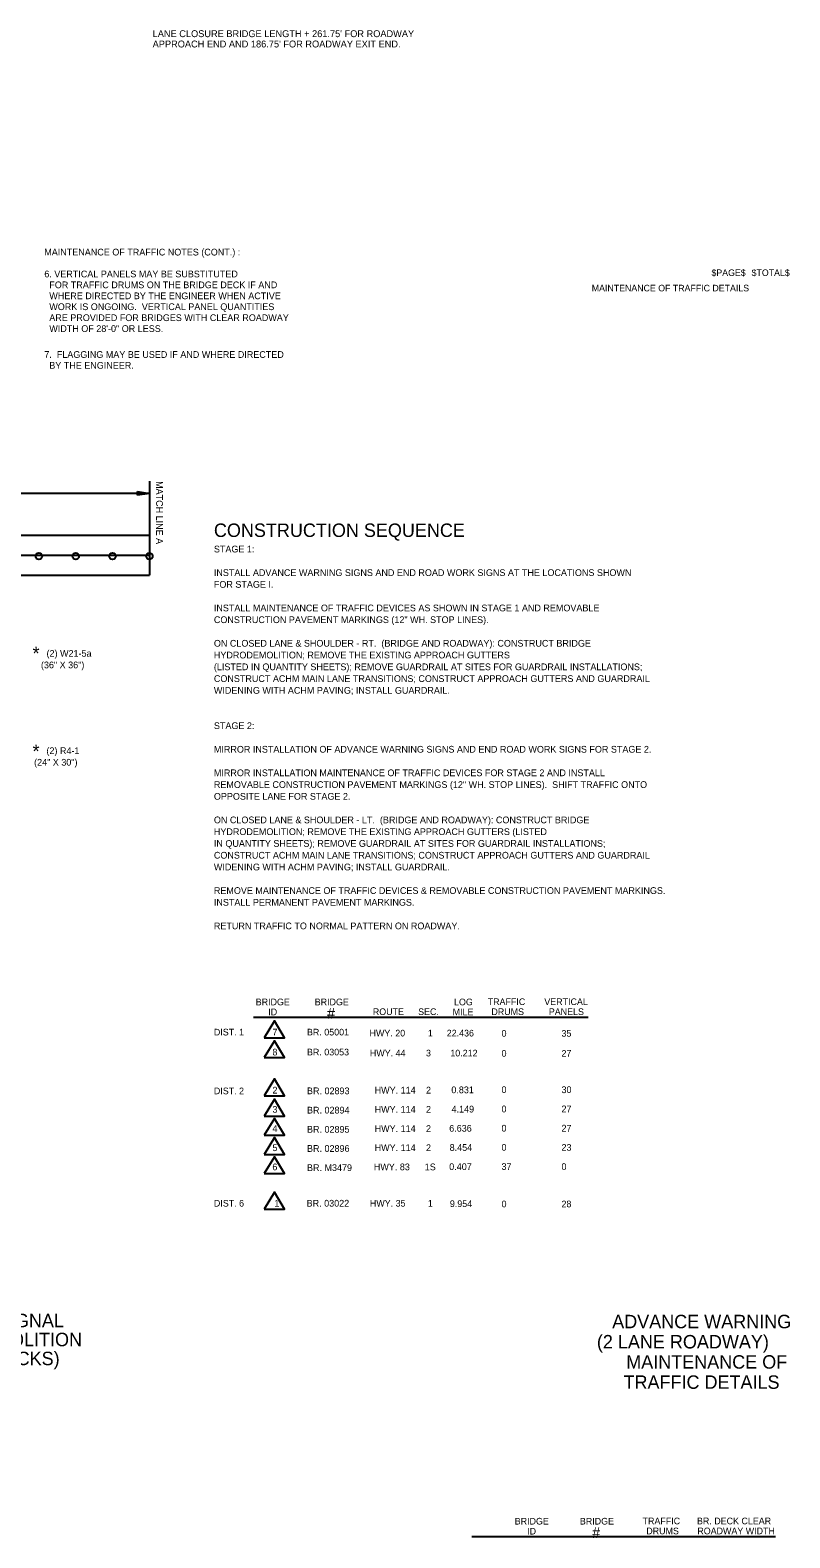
# Model space of a CAD drawing. Extents: x 1925873 to 1930787, y 596452 to 599617.
# Drawn here: x 1928734 to 1929411, y 596543 to 597888 of the extents above; entities that cross this region are included whole.
import ezdxf

# ---------------------------------------------------------------- set-up
doc = ezdxf.new("R2010")
doc.units = 0
for name, color, linetype in [('Default', 7, 'Continuous'), ('R_Border', 7, 'Continuous'), ('R_Border Prem', 7, 'Continuous')]:
    doc.layers.add(name, color=color, linetype=linetype)

msp = doc.modelspace()

# ---------------------------------------------------------------- linework, layer by layer
at = {"layer": 'Default'}
for p, q in [((1928839.9, 597485.4), (1928839.9, 597401.5)), ((1928839.9, 597474.5), (1928347.2, 597474.5)), ((1928829.3, 597472.9), (1928829.3, 597476.1)), ((1928829.3, 597476.1), (1928839.9, 597474.5)), ((1928839.9, 597474.5), (1928829.3, 597472.9)), ((1927951, 597437.1), (1928839.9, 597437.1)), ((1927951, 597419.3), (1928839.9, 597419.3)), ((1927951, 597401.5), (1928839.9, 597401.5)), ((1928942.3, 596989.1), (1928951.3, 596989.1)), ((1928942.3, 596971.3), (1928951.3, 596971.3)), ((1928942.3, 596937.4), (1928951.3, 596937.4)), ((1928942.3, 596919.2), (1928951.3, 596919.2)), ((1928942.3, 596902.1), (1928951.3, 596902.1)), ((1928942.3, 596885), (1928951.3, 596885)), ((1928942.3, 596867.9), (1928951.3, 596867.9)), ((1928942.3, 596836.3), (1928951.3, 596836.3))]:
    msp.add_line(p, q, dxfattribs=at)
for points in [[(1928951.3, 596989.1), (1928960.3, 596989.1), (1928951.3, 597004.1), (1928942.3, 596989.1)], [(1928951.3, 596971.3), (1928960.3, 596971.3), (1928951.3, 596986.3), (1928942.3, 596971.3)], [(1928951.3, 596937.4), (1928960.3, 596937.4), (1928951.3, 596952.4), (1928942.3, 596937.4)], [(1928951.3, 596919.2), (1928960.3, 596919.2), (1928951.3, 596934.2), (1928942.3, 596919.2)], [(1928951.3, 596902.1), (1928960.3, 596902.1), (1928951.3, 596917.1), (1928942.3, 596902.1)], [(1928951.3, 596885), (1928960.3, 596885), (1928951.3, 596900), (1928942.3, 596885)], [(1928951.3, 596867.9), (1928960.3, 596867.9), (1928951.3, 596882.9), (1928942.3, 596867.9)], [(1928951.3, 596836.3), (1928960.3, 596836.3), (1928951.3, 596851.3), (1928942.3, 596836.3)]]:
    msp.add_lwpolyline(points, dxfattribs=at)
for centre in [(1928741.4, 597418.5), (1928774.2, 597418.5), (1928807, 597418.5), (1928839.9, 597418.5)]:
    msp.add_circle(centre, 2.88, dxfattribs=at)
at = {"layer": 'R_Border'}
for p, q in [((1928932.8, 597007.3), (1929231.2, 597007.3)), ((1929127.5, 596544.3), (1929398, 596544.3))]:
    msp.add_line(p, q, dxfattribs=at)

# ---------------------------------------------------------------- texts
at = {"layer": 'Default'}
for s, height, rotation, p in [("LANE CLOSURE BRIDGE LENGTH + 261.75' FOR ROADWAY ", 6.14, 360, (1928842.8, 597881.3)), ("APPROACH END AND 186.75' FOR ROADWAY EXIT END.", 6.14, 360, (1928842.8, 597872.1)), ('MATCH LINE A', 6, 270, (1928845.9, 597485.4)), ('LANE CLOSURE WITH PORTABLE TRAFFIC SIGNAL ', 12, 360, (1928368.7, 596730.9)), ('SYSTEM & TRAFFIC DRUMS FOR HYDRODEMOLITION', 12, 360, (1928362.6, 596714)), ('(VAR. CLEAR ROADWAY ON THE BRIDGE DECKS)', 12, 360, (1928375.6, 596697.1))]:
    msp.add_text(s, height=height, rotation=rotation, dxfattribs=at).set_placement(p)
at = {"layer": 'R_Border'}
for s, height, p in [('MAINTENANCE OF TRAFFIC NOTES (CONT.) :', 6, (1928746.2, 597686.6)), ('6. VERTICAL PANELS MAY BE SUBSTITUTED', 6, (1928746.2, 597667.1)), ('  WHERE DIRECTED BY THE ENGINEER WHEN ACTIVE', 6, (1928746.2, 597647.6)), ('  FOR TRAFFIC DRUMS ON THE BRIDGE DECK IF AND', 6, (1928746.2, 597657.4)), ('  WORK IS ONGOING.  VERTICAL PANEL QUANTITIES', 6, (1928746.2, 597637.9)), ('  ARE PROVIDED FOR BRIDGES WITH CLEAR ROADWAY', 6, (1928746.2, 597628.1)), ('  WIDTH OF 28\'-0" OR LESS.', 6, (1928746.2, 597618.4)), ('7.  FLAGGING MAY BE USED IF AND WHERE DIRECTED', 6, (1928746.2, 597595.3)), ('  BY THE ENGINEER.', 6, (1928746.2, 597585.6)), ('CONSTRUCTION SEQUENCE', 12, (1928897.4, 597435.6)), ('STAGE 1:', 6, (1928897.4, 597421.8)), ('FOR STAGE I.  ', 6, (1928897.4, 597390.3)), ('INSTALL ADVANCE WARNING SIGNS AND END ROAD WORK SIGNS AT THE LOCATIONS SHOWN ', 6, (1928897.4, 597400.8)), ('INSTALL MAINTENANCE OF TRAFFIC DEVICES AS SHOWN IN STAGE 1 AND REMOVABLE ', 6, (1928897.4, 597369.3)), ('CONSTRUCTION PAVEMENT MARKINGS (12" WH. STOP LINES). ', 6, (1928897.4, 597358.8)), ('ON CLOSED LANE & SHOULDER - RT.  (BRIDGE AND ROADWAY): CONSTRUCT BRIDGE ', 6, (1928897.4, 597337.8)), ('(2) W21-5a', 6, (1928748.2, 597328.8)), ('HYDRODEMOLITION; REMOVE THE EXISTING APPROACH GUTTERS ', 6, (1928897.4, 597327.3)), ('(36" X 36")', 6, (1928743.2, 597318.5)), ('(LISTED IN QUANTITY SHEETS); REMOVE GUARDRAIL AT SITES FOR GUARDRAIL INSTALLATIONS; ', 6, (1928897.4, 597316.8)), ('WIDENING WITH ACHM PAVING; INSTALL GUARDRAIL.', 6, (1928897.4, 597295.8)), ('CONSTRUCT ACHM MAIN LANE TRANSITIONS; CONSTRUCT APPROACH GUTTERS AND GUARDRAIL', 6, (1928897.4, 597306.3)), ('STAGE 2:', 6, (1928897.4, 597264.3)), ('(2) R4-1', 6, (1928748.1, 597242)), ('MIRROR INSTALLATION OF ADVANCE WARNING SIGNS AND END ROAD WORK SIGNS FOR STAGE 2.  ', 6, (1928897.4, 597243.3)), ('(24" X 30")', 6, (1928737.1, 597231.7)), ('MIRROR INSTALLATION MAINTENANCE OF TRAFFIC DEVICES FOR STAGE 2 AND INSTALL ', 6, (1928897.4, 597222.3)), ('REMOVABLE CONSTRUCTION PAVEMENT MARKINGS (12" WH. STOP LINES).  SHIFT TRAFFIC ONTO ', 6, (1928897.4, 597211.8)), ('OPPOSITE LANE FOR STAGE 2.', 6, (1928897.4, 597201.3)), ('ON CLOSED LANE & SHOULDER - LT.  (BRIDGE AND ROADWAY): CONSTRUCT BRIDGE ', 6, (1928897.4, 597180.3)), ('HYDRODEMOLITION; REMOVE THE EXISTING APPROACH GUTTERS (LISTED ', 6, (1928897.4, 597169.8)), ('CONSTRUCT ACHM MAIN LANE TRANSITIONS; CONSTRUCT APPROACH GUTTERS AND GUARDRAIL', 6, (1928897.4, 597148.8)), ('IN QUANTITY SHEETS); REMOVE GUARDRAIL AT SITES FOR GUARDRAIL INSTALLATIONS; ', 6, (1928897.4, 597159.3)), ('WIDENING WITH ACHM PAVING; INSTALL GUARDRAIL.', 6, (1928897.4, 597138.3)), ('REMOVE MAINTENANCE OF TRAFFIC DEVICES & REMOVABLE CONSTRUCTION PAVEMENT MARKINGS.  ', 6, (1928897.4, 597117.3)), ('INSTALL PERMANENT PAVEMENT MARKINGS.', 6, (1928897.4, 597106.8)), ('RETURN TRAFFIC TO NORMAL PATTERN ON ROADWAY. ', 6, (1928897.4, 597085.8)), ('BRIDGE ', 5.93, (1928934.7, 597018)), ('BRIDGE ', 5.93, (1928987.3, 597018)), ('LOG', 5.93, (1929111.5, 597018)), ('TRAFFIC ', 5.93, (1929141.5, 597018.2)), ('VERTICAL', 5.93, (1929192, 597018.2)), ('ID', 5.93, (1928945.9, 597009.1)), ('#', 9.5, (1928998.3, 597006.1)), ('ROUTE', 5.93, (1929039.1, 597009.3)), ('SEC.', 5.93, (1929079.5, 597009.3)), ('MILE', 5.93, (1929110.3, 597009.1)), ('DRUMS', 5.93, (1929144.8, 597009.3)), ('PANELS', 5.93, (1929196, 597009.3)), ('DIST. 1', 5.93, (1928897.4, 596991.1)), ('7', 5.93, (1928949.6, 596991.1)), ('BR. 05001', 5.93, (1928980.4, 596991.1)), ('HWY. 20', 5.93, (1929036.2, 596990.2)), ('1', 5.93, (1929088.2, 596990.2)), ('22.436', 5.93, (1929105, 596990.2)), ('0', 5.93, (1929153.9, 596990)), ('35', 5.93, (1929207.3, 596990)), ('8', 5.93, (1928949.6, 596973.3)), ('BR. 03053', 5.93, (1928980.4, 596973.3)), ('HWY. 44', 5.93, (1929036.5, 596972.4)), ('3', 5.93, (1929086.5, 596972.4)), ('10.212', 5.93, (1929108.2, 596972.4)), ('0', 5.93, (1929153.9, 596972.2)), ('27', 5.93, (1929207.3, 596972.2)), ('DIST. 2', 5.93, (1928897.4, 596938.7)), ('2', 6, (1928949.6, 596939.3)), ('BR. 02893', 6, (1928980.4, 596938.7)), ('HWY. 114', 6, (1929040.7, 596939.3)), ('2', 6, (1929086.5, 596939.3)), ('0.831', 6, (1929109.1, 596939.6)), ('0', 6, (1929153.8, 596939.7)), ('30', 6, (1929207.3, 596939.7)), ('3', 6, (1928949.6, 596922.2)), ('BR. 02894 ', 6, (1928980.4, 596921.5)), ('HWY. 114', 6, (1929040.7, 596922.2)), ('2', 6, (1929086.5, 596922.2)), ('4.149', 6, (1929109.3, 596922.4)), ('0', 6, (1929153.8, 596922.6)), ('27', 6, (1929207.3, 596922.6)), ('4', 6, (1928949.6, 596905.1)), ('BR. 02895', 6, (1928980.4, 596904.4)), ('HWY. 114', 6, (1929040.7, 596905.1)), ('2', 6, (1929086.5, 596905.1)), ('6.636', 6, (1929107.2, 596905.3)), ('0', 6, (1929153.8, 596905.4)), ('27', 6, (1929207.3, 596905.4)), ('5', 6, (1928949.6, 596888)), ('BR. 02896', 6, (1928980.4, 596887.3)), ('HWY. 114', 6, (1929040.7, 596888)), ('2', 6, (1929086.5, 596888)), ('8.454', 6, (1929107.6, 596888.2)), ('0', 6, (1929153.8, 596888.3)), ('23', 6, (1929207.3, 596888.3)), ('6', 6, (1928949.5, 596870.9)), ('BR. M3479', 6, (1928980.4, 596870.2)), ('HWY. 83', 6, (1929040, 596870.9)), ('1S', 6, (1929085.4, 596870.9)), ('0.407', 6, (1929107.2, 596871.1)), ('37', 6, (1929153.8, 596871.2)), ('0', 6, (1929207.3, 596871.2)), ('DIST. 6', 5.93, (1928897.4, 596838.5)), ('1', 6, (1928951.3, 596838.5)), ('BR. 03022', 6, (1928980.1, 596838.5)), ('HWY. 35', 5.93, (1929036.5, 596838.5)), ('1', 5.93, (1929088.2, 596838.5)), ('9.954', 5.93, (1929107.8, 596838.1)), ('0', 5.93, (1929153.9, 596837.9)), ('28', 5.93, (1929207.3, 596837.9)), ('ADVANCE WARNING', 12, (1929252.5, 596730)), (' (2 LANE ROADWAY) ', 12, (1929234.4, 596712)), ('MAINTENANCE OF ', 12, (1929265, 596694)), ('TRAFFIC DETAILS', 12, (1929262.6, 596676)), ('BRIDGE ', 5.93, (1929165.6, 596555)), ('ID', 5.93, (1929176.7, 596546.1)), ('BRIDGE ', 5.93, (1929223.7, 596555)), ('#', 9.5, (1929234.7, 596543.1)), ('TRAFFIC ', 5.93, (1929279.6, 596555.2)), ('DRUMS', 5.93, (1929282.9, 596546.3)), ('BR. DECK CLEAR', 5.929, (1929328.1, 596555.2)), ('ROADWAY WIDTH', 5.929, (1929328.4, 596546.3))]:
    msp.add_text(s, height=height, rotation=360, dxfattribs=at).set_placement(p)
at = {"layer": 'R_Border Prem'}
for s, height, p in [('$PAGE$', 5.86, (1929341, 597668.3)), ('$TOTAL$', 5.86, (1929376.8, 597668.3)), ('MAINTENANCE OF TRAFFIC DETAILS', 5.862, (1929234.3, 597654.6)), ('*', 12, (1928735.7, 597325.8)), ('*', 12, (1928735.7, 597238.5))]:
    msp.add_text(s, height=height, rotation=360, dxfattribs=at).set_placement(p)

doc.saveas('drawing.dxf')
